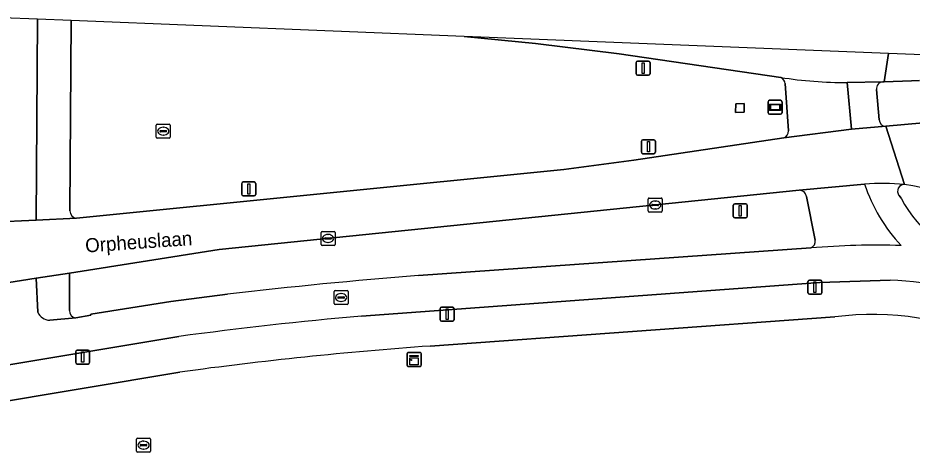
# Model space of a CAD drawing. Extents: x 161758 to 162722, y 384793 to 385405.
# Drawn here: x 161913.2 to 161977.1, y 385354.7 to 385385.7 of the extents above; entities that cross this region are included whole.
import ezdxf

# ---------------------------------------------------------------- set-up
doc = ezdxf.new("R2010")
doc.units = 0
for name, color, linetype in [('IMGEO_Berm_gesloten', 7, 'Continuous'), ('IMGEO_Berm_groen', 7, 'Continuous'), ('IMGEO_Fietspad_gesloten', 7, 'Continuous'), ('IMGEO_Groenvoorziening', 7, 'Continuous'), ('IMGEO_Kast', 7, 'Continuous'), ('IMGEO_Kolk', 7, 'Continuous'), ('IMGEO_Lichtmast', 7, 'Continuous'), ('IMGEO_Openbare_ruimte_label', 7, 'Continuous'), ('IMGEO_Rijbaan_lokaal_gesloten', 7, 'Continuous'), ('IMGEO_Rioolput', 7, 'Continuous'), ('IMGEO_Straatnaambord', 7, 'Continuous'), ('IMGEO_Terreindeel_open', 7, 'Continuous'), ('IMGEO_Verkeersbordpaal', 7, 'Continuous'), ('IMGEO_Verkeerseiland_gesloten', 7, 'Continuous'), ('IMGEO_Voetpad_open', 7, 'Continuous')]:
    doc.layers.add(name, color=color, linetype=linetype)

msp = doc.modelspace()

# ---------------------------------------------------------------- linework, layer by layer
at = {"layer": 'IMGEO_Berm_gesloten'}
msp.add_lwpolyline([(161976.151, 385373.042), (161976.299, 385372.83)], dxfattribs=at)
for centre, radius, start, end in [((161976.532, 385373.339), 0.483, 87.56385, 217.90438), ((161974.637, 385360.427), 13.531, 42.06056, 81.86032), ((161984.403, 385377.16), 9.188, 208.11884, 257.97269)]:
    msp.add_arc(centre, radius, start, end, dxfattribs=at)
at = {"layer": 'IMGEO_Berm_groen'}
for points in [[(161945.103, 385384.393), (161917.049, 385385.522), (161916.952, 385371.936)], [(161967.708, 385381.461), (161956.161, 385383.144), (161950.192, 385383.892), (161945.103, 385384.393)], [(161968.253, 385377.641), (161968.024, 385381.02)], [(161917.416, 385371.401), (161952.219, 385374.897), (161957.216, 385375.545), (161967.929, 385377.148)], [(161969.028, 385373.402), (161927.597, 385369.17), (161916.923, 385367.494), (161916.916, 385364.811)], [(161970.163, 385369.853), (161969.539, 385372.958)], [(161941.846, 385367.307), (161969.866, 385369.286)], [(161917.367, 385364.291), (161918.442, 385364.486), (161918.434, 385364.558), (161924.166, 385365.467), (161928.204, 385365.982)]]:
    msp.add_lwpolyline(points, dxfattribs=at)
msp.add_lwpolyline([(161964.504, 385379.586), (161965.1, 385379.595), (161965.105, 385378.974), (161964.466, 385378.952)], close=True, dxfattribs=at)
for centre, radius, start, end in [((161967.467, 385380.954), 0.561, 6.7151, 64.53213), ((161967.777, 385377.601), 0.477, 288.51413, 4.85997), ((161969.053, 385372.915), 0.488, 5.1004, 92.92586), ((161917.53, 385371.969), 0.579, 183.2499, 258.61963), ((161969.646, 385369.762), 0.525, 294.7652, 9.94285), ((161968.474, 385022.259), 346.074, 94.41287, 96.68221), ((161917.428, 385364.799), 0.512, 178.69969, 263.17101)]:
    msp.add_arc(centre, radius, start, end, dxfattribs=at)
at = {"layer": 'IMGEO_Fietspad_gesloten'}
for points in [[(161911.4, 385371.127), (161914.544, 385371.27), (161914.64, 385385.619), (161912.146, 385385.719)], [(161974.985, 385381.151), (161972.454, 385381.101), (161972.759, 385377.761), (161975.203, 385377.974)], [(161974.742, 385378.438), (161974.546, 385380.611)], [(161976.299, 385372.83), (161976.151, 385373.042)], [(161969.866, 385369.286), (161941.846, 385367.307)], [(161914.653, 385364.708), (161914.537, 385367.119), (161912.002, 385366.721), (161911.851, 385366.698), (161911.988, 385366.021), (161911.987, 385365.957), (161911.985, 385365.893), (161911.981, 385365.829)], [(161937.781, 385364.42), (161970.497, 385366.829), (161975.511, 385366.99)], [(161928.204, 385365.982), (161924.166, 385365.467), (161918.434, 385364.558), (161918.442, 385364.486), (161917.367, 385364.291), (161915.514, 385364.129)], [(161909.275, 385360.387), (161924.722, 385362.965)]]:
    msp.add_lwpolyline(points, dxfattribs=at)
for centre, radius, start, end in [((161975.027, 385380.669), 0.484, 94.94392, 186.83642), ((161975.206, 385378.438), 0.464, 180.04152, 269.58683), ((161975.002, 385356.017), 17.873, 85.02278, 94.21729), ((161985.393, 385377.833), 12.367, 198.83171, 222.65699), ((161976.532, 385373.339), 0.483, 87.56385, 217.90438), ((161984.403, 385377.16), 9.188, 208.11884, 257.97269), ((161974.487, 385315.26), 54.223, 88.0859, 94.88867), ((161968.474, 385022.259), 346.074, 94.41287, 96.68221), ((161974.467, 385343.268), 23.745, 65.72803, 87.48046), ((161915.506, 385365.047), 0.918, 201.65335, 270.50705), ((161964.956, 385061.189), 304.447, 95.121, 97.59406)]:
    msp.add_arc(centre, radius, start, end, dxfattribs=at)
at = {"layer": 'IMGEO_Groenvoorziening'}
for points in [[(161971.573, 385364.366), (161942.672, 385362.279)], [(161924.792, 385360.416), (161910.683, 385358.067)]]:
    msp.add_lwpolyline(points, dxfattribs=at)
for centre, radius, start, end in [((161974.266, 385343.076), 21.459, 65.15824, 97.20826), ((161963.563, 385075.051), 287.987, 94.15989, 97.73701)]:
    msp.add_arc(centre, radius, start, end, dxfattribs=at)
at = {"layer": 'IMGEO_Kast'}
for p, q in [((161941.029, 385360.894), (161941.029, 385361.735)), ((161941.029, 385361.735), (161941.029, 385360.894)), ((161941.104, 385361.819), (161941.945, 385361.819)), ((161941.945, 385361.819), (161941.104, 385361.819)), ((161942.029, 385361.744), (161942.029, 385360.903)), ((161942.029, 385360.903), (161942.029, 385361.744)), ((161941.954, 385360.819), (161941.113, 385360.819)), ((161941.113, 385360.819), (161941.954, 385360.819))]:
    msp.add_line(p, q, dxfattribs=at)
for points in [[(161941.224, 385361.609), (161941.824, 385361.609), (161941.824, 385361.524), (161941.224, 385361.524), (161941.224, 385361.609)], [(161941.224, 385361.434), (161941.824, 385361.434), (161941.824, 385360.945), (161941.224, 385360.945), (161941.224, 385361.434)]]:
    msp.add_lwpolyline(points, dxfattribs=at)
msp.add_circle((161941.308, 385361.283), 0.0377, dxfattribs=at)
for centre, start, end in [((161941.107, 385361.741), 92.4484, 184.28452), ((161941.107, 385361.741), 92.4484, 184.28452), ((161941.951, 385361.741), 2.4484, 94.28452), ((161941.951, 385361.741), 2.4484, 94.28452), ((161941.107, 385360.897), 182.4484, 274.28452), ((161941.107, 385360.897), 182.4484, 274.28452), ((161941.951, 385360.897), 272.4484, 4.28452), ((161941.951, 385360.897), 272.4484, 4.28452)]:
    msp.add_arc(centre, 0.0779, start, end, dxfattribs=at)
at = {"layer": 'IMGEO_Kolk'}
for p, q in [((161958.244, 385371.926), (161958.244, 385372.778)), ((161958.319, 385372.852), (161959.171, 385372.852)), ((161959.245, 385372.778), (161959.245, 385371.926)), ((161958.503, 385372.346), (161958.503, 385372.358)), ((161958.941, 385372.309), (161958.543, 385372.309)), ((161958.546, 385372.395), (161958.944, 385372.395)), ((161958.732, 385372.632), (161958.757, 385372.632)), ((161958.987, 385372.358), (161958.987, 385372.346)), ((161959.171, 385371.852), (161958.319, 385371.852)), ((161958.755, 385372.072), (161958.73, 385372.072)), ((161934.882, 385369.539), (161934.882, 385370.391)), ((161934.957, 385370.465), (161935.809, 385370.465)), ((161935.37, 385370.245), (161935.395, 385370.245)), ((161935.883, 385370.391), (161935.883, 385369.539)), ((161935.141, 385369.959), (161935.141, 385369.971)), ((161935.579, 385369.922), (161935.181, 385369.922)), ((161935.184, 385370.008), (161935.582, 385370.008)), ((161935.393, 385369.685), (161935.368, 385369.685)), ((161935.625, 385369.971), (161935.625, 385369.959)), ((161935.809, 385369.465), (161934.957, 385369.465))]:
    msp.add_line(p, q, dxfattribs=at)
for points in [[(161958.244, 385371.926), (161958.244, 385372.778)], [(161958.319, 385372.852), (161959.171, 385372.852)], [(161959.245, 385372.778), (161959.245, 385371.926)], [(161959.171, 385371.852), (161958.319, 385371.852)], [(161934.882, 385369.539), (161934.882, 385370.391)], [(161934.957, 385370.465), (161935.809, 385370.465)], [(161935.883, 385370.391), (161935.883, 385369.539)], [(161935.809, 385369.465), (161934.957, 385369.465)]]:
    msp.add_lwpolyline(points, dxfattribs=at)
for centre, radius, start, end in [((161958.321, 385372.776), 0.0765, 91.55205, 178.44795), ((161958.321, 385372.776), 0.0765, 91.55205, 178.44795), ((161959.169, 385372.776), 0.0765, 1.55205, 88.44795), ((161959.169, 385372.776), 0.0765, 1.55205, 88.44795), ((161958.543, 385372.355), 0.0403, 85.87752, 175.75265), ((161958.54, 385372.345), 0.0366, 178.93798, 274.71019), ((161958.944, 385372.352), 0.043, 264.86636, 352.45326), ((161958.948, 385372.357), 0.0386, 1.73085, 96.63898), ((161958.321, 385371.928), 0.0765, 181.55205, 268.44795), ((161958.321, 385371.928), 0.0765, 181.55205, 268.44795), ((161959.169, 385371.928), 0.0765, 271.55205, 358.44795), ((161959.169, 385371.928), 0.0765, 271.55205, 358.44795), ((161934.959, 385370.389), 0.0765, 91.55205, 178.44795), ((161934.959, 385370.389), 0.0765, 91.55205, 178.44795), ((161935.807, 385370.389), 0.0765, 1.55205, 88.44795), ((161935.807, 385370.389), 0.0765, 1.55205, 88.44795), ((161935.181, 385369.968), 0.0403, 85.87752, 175.75265), ((161935.178, 385369.958), 0.0366, 178.93798, 274.71019), ((161935.582, 385369.965), 0.043, 264.86636, 352.45326), ((161935.586, 385369.97), 0.0386, 1.73085, 96.63898), ((161934.959, 385369.541), 0.0765, 181.55205, 268.44795), ((161934.959, 385369.541), 0.0765, 181.55205, 268.44795), ((161935.807, 385369.541), 0.0765, 271.55205, 358.44795), ((161935.807, 385369.541), 0.0765, 271.55205, 358.44795)]:
    msp.add_arc(centre, radius, start, end, dxfattribs=at)
for centre, major_axis, ratio, start_param, end_param in [((161958.731, 385372.352), (-0.387, 0.002), 0.722429, 4.712389, 7.853982), ((161958.756, 385372.352), (-0.39, 0.002), 0.717154, 1.570796, 4.712389), ((161935.369, 385369.965), (-0.387, 0.002), 0.722429, 4.712389, 7.853982), ((161935.394, 385369.965), (-0.39, 0.002), 0.717154, 1.570796, 4.712389)]:
    msp.add_ellipse(centre, major_axis=major_axis, ratio=ratio, start_param=start_param, end_param=end_param, dxfattribs=at)
at = {"layer": 'IMGEO_Lichtmast'}
for p, q in [((161957.384, 385381.724), (161957.384, 385382.524)), ((161957.384, 385382.524), (161957.384, 385381.724)), ((161957.484, 385382.624), (161958.274, 385382.624)), ((161958.274, 385382.624), (161957.484, 385382.624)), ((161958.374, 385382.524), (161958.374, 385381.724)), ((161958.374, 385381.724), (161958.374, 385382.524)), ((161958.274, 385381.624), (161957.484, 385381.624)), ((161957.484, 385381.624), (161958.274, 385381.624)), ((161957.762, 385376.116), (161957.762, 385376.916)), ((161957.762, 385376.916), (161957.762, 385376.116)), ((161957.862, 385377.016), (161958.652, 385377.016)), ((161958.652, 385377.016), (161957.862, 385377.016)), ((161958.752, 385376.916), (161958.752, 385376.116)), ((161958.752, 385376.116), (161958.752, 385376.916)), ((161958.652, 385376.016), (161957.862, 385376.016)), ((161957.862, 385376.016), (161958.652, 385376.016)), ((161929.225, 385373.098), (161929.225, 385373.898)), ((161929.225, 385373.898), (161929.225, 385373.098)), ((161929.325, 385373.998), (161930.115, 385373.998)), ((161930.115, 385373.998), (161929.325, 385373.998)), ((161930.215, 385373.898), (161930.215, 385373.098)), ((161930.215, 385373.098), (161930.215, 385373.898)), ((161930.115, 385372.998), (161929.325, 385372.998)), ((161929.325, 385372.998), (161930.115, 385372.998)), ((161969.651, 385366.081), (161969.651, 385366.881)), ((161969.651, 385366.881), (161969.651, 385366.081)), ((161969.751, 385366.981), (161970.541, 385366.981)), ((161970.541, 385366.981), (161969.751, 385366.981)), ((161970.641, 385366.881), (161970.641, 385366.081)), ((161970.641, 385366.081), (161970.641, 385366.881)), ((161970.541, 385365.981), (161969.751, 385365.981)), ((161969.751, 385365.981), (161970.541, 385365.981)), ((161943.39, 385364.155), (161943.39, 385364.955)), ((161943.39, 385364.955), (161943.39, 385364.155)), ((161943.49, 385365.055), (161944.28, 385365.055)), ((161944.28, 385365.055), (161943.49, 385365.055)), ((161944.38, 385364.955), (161944.38, 385364.155)), ((161944.38, 385364.155), (161944.38, 385364.955)), ((161944.28, 385364.055), (161943.49, 385364.055)), ((161943.49, 385364.055), (161944.28, 385364.055)), ((161917.461, 385361.995), (161918.251, 385361.995)), ((161918.251, 385361.995), (161917.461, 385361.995)), ((161917.361, 385361.095), (161917.361, 385361.895)), ((161917.361, 385361.895), (161917.361, 385361.095)), ((161918.351, 385361.895), (161918.351, 385361.095)), ((161918.351, 385361.095), (161918.351, 385361.895)), ((161918.251, 385360.995), (161917.461, 385360.995)), ((161917.461, 385360.995), (161918.251, 385360.995))]:
    msp.add_line(p, q, dxfattribs=at)
for points in [[(161957.804, 385382.499), (161957.954, 385382.499), (161957.954, 385381.749), (161957.804, 385381.749), (161957.804, 385382.499)], [(161958.182, 385376.891), (161958.332, 385376.891), (161958.332, 385376.141), (161958.182, 385376.141), (161958.182, 385376.891)], [(161929.645, 385373.873), (161929.795, 385373.873), (161929.795, 385373.123), (161929.645, 385373.123), (161929.645, 385373.873)], [(161970.071, 385366.856), (161970.221, 385366.856), (161970.221, 385366.106), (161970.071, 385366.106), (161970.071, 385366.856)], [(161943.81, 385364.93), (161943.96, 385364.93), (161943.96, 385364.18), (161943.81, 385364.18), (161943.81, 385364.93)], [(161917.781, 385361.87), (161917.931, 385361.87), (161917.931, 385361.12), (161917.781, 385361.12), (161917.781, 385361.87)]]:
    msp.add_lwpolyline(points, dxfattribs=at)
for centre, start, end in [((161957.484, 385382.524), 90, 180), ((161957.484, 385382.524), 90, 180), ((161958.274, 385382.524), 0, 90), ((161958.274, 385382.524), 360, 90), ((161957.484, 385381.724), 180, 270), ((161957.484, 385381.724), 180, 270), ((161958.274, 385381.724), 270, 0), ((161958.274, 385381.724), 270, 0), ((161957.862, 385376.916), 90, 180), ((161957.862, 385376.916), 90, 180), ((161958.652, 385376.916), 0, 90), ((161958.652, 385376.916), 360, 90), ((161957.862, 385376.116), 180, 270), ((161957.862, 385376.116), 180, 270), ((161958.652, 385376.116), 270, 0), ((161958.652, 385376.116), 270, 0), ((161929.325, 385373.898), 90, 180), ((161929.325, 385373.898), 90, 180), ((161930.115, 385373.898), 0, 90), ((161930.115, 385373.898), 360, 90), ((161929.325, 385373.098), 180, 270), ((161929.325, 385373.098), 180, 270), ((161930.115, 385373.098), 270, 0), ((161930.115, 385373.098), 270, 0), ((161969.751, 385366.881), 90, 180), ((161969.751, 385366.881), 90, 180), ((161970.541, 385366.881), 0, 90), ((161970.541, 385366.881), 360, 90), ((161969.751, 385366.081), 180, 270), ((161969.751, 385366.081), 180, 270), ((161970.541, 385366.081), 270, 0), ((161970.541, 385366.081), 270, 0), ((161943.49, 385364.955), 90, 180), ((161943.49, 385364.955), 90, 180), ((161944.28, 385364.955), 0, 90), ((161944.28, 385364.955), 360, 90), ((161943.49, 385364.155), 180, 270), ((161943.49, 385364.155), 180, 270), ((161944.28, 385364.155), 270, 0), ((161944.28, 385364.155), 270, 0), ((161917.461, 385361.895), 90, 180), ((161917.461, 385361.895), 90, 180), ((161918.251, 385361.895), 0, 90), ((161918.251, 385361.895), 360, 90), ((161917.461, 385361.095), 180, 270), ((161917.461, 385361.095), 180, 270), ((161918.251, 385361.095), 270, 0), ((161918.251, 385361.095), 270, 0)]:
    msp.add_arc(centre, 0.1, start, end, dxfattribs=at)
at = {"layer": 'IMGEO_Rijbaan_lokaal_gesloten'}
for points in [[(161975.392, 385383.175), (161945.103, 385384.393), (161950.192, 385383.892), (161956.161, 385383.144), (161967.708, 385381.461)], [(161972.454, 385381.101), (161974.985, 385381.151), (161975.099, 385381.155), (161975.392, 385383.175)], [(161975.392, 385383.175), (161975.099, 385381.155), (161977.036, 385381.228), (161977.622, 385381.235)], [(161985.172, 385382.782), (161975.392, 385383.175)], [(161976.553, 385373.822), (161975.203, 385377.974), (161972.759, 385377.761), (161967.929, 385377.148), (161957.216, 385375.545), (161952.219, 385374.897), (161917.416, 385371.401), (161914.544, 385371.27), (161911.4, 385371.127), (161911.18, 385371.117), (161905.327, 385370.85)], [(161977.887, 385378.221), (161975.203, 385377.974), (161976.553, 385373.822)], [(161890.228, 385372.905), (161889.159, 385372.498), (161888.671, 385372.472), (161887.405, 385372.41), (161886.93, 385365.469), (161891.907, 385365.74), (161899.549, 385366.47), (161904.533, 385366.946), (161911.851, 385366.698), (161912.002, 385366.721), (161914.537, 385367.119), (161916.923, 385367.494), (161927.597, 385369.17), (161969.028, 385373.402)], [(161969.028, 385373.402), (161973.688, 385373.841)]]:
    msp.add_lwpolyline(points, dxfattribs=at)
for centre, radius, start, end in [((161972.504, 385413.223), 32.122, 261.4135, 269.91096), ((161975.002, 385356.017), 17.873, 85.02278, 94.21729), ((161974.637, 385360.427), 13.531, 42.06056, 81.86032)]:
    msp.add_arc(centre, radius, start, end, dxfattribs=at)
at = {"layer": 'IMGEO_Rioolput'}
for p, q in [((161923.114, 385377.199), (161923.114, 385378.051)), ((161923.189, 385378.125), (161924.041, 385378.125)), ((161923.602, 385377.905), (161923.627, 385377.905)), ((161924.115, 385378.051), (161924.115, 385377.199)), ((161923.373, 385377.619), (161923.373, 385377.631)), ((161923.811, 385377.582), (161923.413, 385377.582)), ((161923.416, 385377.668), (161923.814, 385377.668)), ((161923.625, 385377.345), (161923.6, 385377.345)), ((161923.857, 385377.631), (161923.857, 385377.619)), ((161924.041, 385377.125), (161923.189, 385377.125)), ((161935.812, 385365.317), (161935.812, 385366.169)), ((161935.887, 385366.243), (161936.739, 385366.243)), ((161936.071, 385365.737), (161936.071, 385365.749)), ((161936.114, 385365.786), (161936.512, 385365.786)), ((161936.3, 385366.023), (161936.325, 385366.023)), ((161936.555, 385365.749), (161936.555, 385365.737)), ((161936.813, 385366.169), (161936.813, 385365.317)), ((161936.739, 385365.243), (161935.887, 385365.243)), ((161936.509, 385365.7), (161936.111, 385365.7)), ((161936.323, 385365.463), (161936.298, 385365.463)), ((161921.709, 385354.776), (161921.709, 385355.628)), ((161921.784, 385355.702), (161922.636, 385355.702)), ((161922.71, 385355.628), (161922.71, 385354.776)), ((161921.968, 385355.196), (161921.968, 385355.208)), ((161922.406, 385355.159), (161922.008, 385355.159)), ((161922.011, 385355.245), (161922.409, 385355.245)), ((161922.22, 385354.922), (161922.195, 385354.922)), ((161922.197, 385355.482), (161922.222, 385355.482)), ((161922.452, 385355.208), (161922.452, 385355.196)), ((161922.636, 385354.702), (161921.784, 385354.702))]:
    msp.add_line(p, q, dxfattribs=at)
for points in [[(161923.114, 385377.199), (161923.114, 385378.051)], [(161923.189, 385378.125), (161924.041, 385378.125)], [(161924.115, 385378.051), (161924.115, 385377.199)], [(161924.041, 385377.125), (161923.189, 385377.125)], [(161935.812, 385365.317), (161935.812, 385366.169)], [(161935.887, 385366.243), (161936.739, 385366.243)], [(161936.813, 385366.169), (161936.813, 385365.317)], [(161936.739, 385365.243), (161935.887, 385365.243)], [(161921.709, 385354.776), (161921.709, 385355.628)], [(161921.784, 385355.702), (161922.636, 385355.702)], [(161922.71, 385355.628), (161922.71, 385354.776)], [(161922.636, 385354.702), (161921.784, 385354.702)]]:
    msp.add_lwpolyline(points, dxfattribs=at)
for centre, radius, start, end in [((161923.191, 385378.049), 0.0765, 91.55205, 178.44795), ((161923.191, 385378.049), 0.0765, 91.55205, 178.44795), ((161924.039, 385378.049), 0.0765, 1.55205, 88.44795), ((161924.039, 385378.049), 0.0765, 1.55205, 88.44795), ((161923.413, 385377.628), 0.0403, 85.87752, 175.75265), ((161923.41, 385377.618), 0.0366, 178.93798, 274.71019), ((161923.814, 385377.625), 0.043, 264.86636, 352.45326), ((161923.818, 385377.63), 0.0386, 1.73085, 96.63898), ((161923.191, 385377.201), 0.0765, 181.55205, 268.44795), ((161923.191, 385377.201), 0.0765, 181.55205, 268.44795), ((161924.039, 385377.201), 0.0765, 271.55205, 358.44795), ((161924.039, 385377.201), 0.0765, 271.55205, 358.44795), ((161935.889, 385366.167), 0.0765, 91.55205, 178.44795), ((161935.889, 385366.167), 0.0765, 91.55205, 178.44795), ((161936.111, 385365.746), 0.0403, 85.87752, 175.75265), ((161936.516, 385365.748), 0.0386, 1.73085, 96.63898), ((161936.737, 385366.167), 0.0765, 1.55205, 88.44795), ((161936.737, 385366.167), 0.0765, 1.55205, 88.44795), ((161935.889, 385365.319), 0.0765, 181.55205, 268.44795), ((161935.889, 385365.319), 0.0765, 181.55205, 268.44795), ((161936.108, 385365.736), 0.0366, 178.93798, 274.71019), ((161936.512, 385365.743), 0.043, 264.86636, 352.45326), ((161936.737, 385365.319), 0.0765, 271.55205, 358.44795), ((161936.737, 385365.319), 0.0765, 271.55205, 358.44795), ((161921.786, 385355.626), 0.0765, 91.55205, 178.44795), ((161921.786, 385355.626), 0.0765, 91.55205, 178.44795), ((161922.634, 385355.626), 0.0765, 1.55205, 88.44795), ((161922.634, 385355.626), 0.0765, 1.55205, 88.44795), ((161922.008, 385355.205), 0.0403, 85.87752, 175.75265), ((161922.005, 385355.195), 0.0366, 178.93798, 274.71019), ((161922.409, 385355.202), 0.043, 264.86636, 352.45326), ((161922.413, 385355.207), 0.0386, 1.73085, 96.63898), ((161921.786, 385354.778), 0.0765, 181.55205, 268.44795), ((161921.786, 385354.778), 0.0765, 181.55205, 268.44795), ((161922.634, 385354.778), 0.0765, 271.55205, 358.44795), ((161922.634, 385354.778), 0.0765, 271.55205, 358.44795)]:
    msp.add_arc(centre, radius, start, end, dxfattribs=at)
for centre, major_axis, ratio, start_param, end_param in [((161923.601, 385377.625), (-0.387, 0.002), 0.722429, 4.712389, 7.853982), ((161923.626, 385377.625), (-0.39, 0.002), 0.717154, 1.570796, 4.712389), ((161936.299, 385365.743), (-0.387, 0.002), 0.722429, 4.712389, 7.853982), ((161936.324, 385365.743), (-0.39, 0.002), 0.717154, 1.570796, 4.712389), ((161922.196, 385355.202), (-0.387, 0.002), 0.722429, 4.712389, 7.853982), ((161922.221, 385355.202), (-0.39, 0.002), 0.717154, 1.570796, 4.712389)]:
    msp.add_ellipse(centre, major_axis=major_axis, ratio=ratio, start_param=start_param, end_param=end_param, dxfattribs=at)
at = {"layer": 'IMGEO_Straatnaambord'}
for p, q in [((161966.909, 385379.833), (161967.699, 385379.833)), ((161967.699, 385379.833), (161966.909, 385379.833)), ((161966.809, 385378.933), (161966.809, 385379.733)), ((161966.809, 385379.733), (161966.809, 385378.933)), ((161967.799, 385379.733), (161967.799, 385378.933)), ((161967.799, 385378.933), (161967.799, 385379.733)), ((161967.699, 385378.833), (161966.909, 385378.833)), ((161966.909, 385378.833), (161967.699, 385378.833))]:
    msp.add_line(p, q, dxfattribs=at)
for points in [[(161966.91, 385379.565), (161967.698, 385379.565), (161967.698, 385379.101), (161966.91, 385379.101), (161966.91, 385379.565)], [(161966.975, 385379.5), (161966.975, 385379.166), (161967.633, 385379.166), (161967.633, 385379.5), (161966.975, 385379.5)]]:
    msp.add_lwpolyline(points, dxfattribs=at)
for centre, start, end in [((161966.909, 385379.733), 90, 180), ((161966.909, 385379.733), 90, 180), ((161967.699, 385379.733), 0, 90), ((161967.699, 385379.733), 360, 90), ((161966.909, 385378.933), 180, 270), ((161966.909, 385378.933), 180, 270), ((161967.699, 385378.933), 270, 0), ((161967.699, 385378.933), 270, 0)]:
    msp.add_arc(centre, 0.1, start, end, dxfattribs=at)
at = {"layer": 'IMGEO_Terreindeel_open'}
msp.add_lwpolyline([(161965.105, 385378.974), (161965.1, 385379.595), (161964.504, 385379.586), (161964.466, 385378.952)], close=True, dxfattribs=at)
at = {"layer": 'IMGEO_Verkeersbordpaal'}
for p, q in [((161964.317, 385371.54), (161964.317, 385372.34)), ((161964.317, 385372.34), (161964.317, 385371.54)), ((161964.417, 385372.44), (161965.207, 385372.44)), ((161965.207, 385372.44), (161964.417, 385372.44)), ((161965.307, 385372.34), (161965.307, 385371.54)), ((161965.307, 385371.54), (161965.307, 385372.34)), ((161965.207, 385371.44), (161964.417, 385371.44)), ((161964.417, 385371.44), (161965.207, 385371.44))]:
    msp.add_line(p, q, dxfattribs=at)
msp.add_lwpolyline([(161964.737, 385372.315), (161964.887, 385372.315), (161964.887, 385371.565), (161964.737, 385371.565), (161964.737, 385372.315)], dxfattribs=at)
for centre, start, end in [((161964.417, 385372.34), 90, 180), ((161964.417, 385372.34), 90, 180), ((161965.207, 385372.34), 0, 90), ((161965.207, 385372.34), 360, 90), ((161964.417, 385371.54), 180, 270), ((161964.417, 385371.54), 180, 270), ((161965.207, 385371.54), 270, 0), ((161965.207, 385371.54), 270, 0)]:
    msp.add_arc(centre, 0.1, start, end, dxfattribs=at)
at = {"layer": 'IMGEO_Verkeerseiland_gesloten'}
for points in [[(161977.622, 385381.235), (161977.036, 385381.228), (161975.099, 385381.155), (161974.985, 385381.151)], [(161974.546, 385380.611), (161974.742, 385378.438)], [(161975.203, 385377.974), (161977.887, 385378.221)]]:
    msp.add_lwpolyline(points, dxfattribs=at)
for centre, radius, start, end in [((161975.027, 385380.669), 0.484, 94.94392, 186.83642), ((161975.206, 385378.438), 0.464, 180.04152, 269.58683)]:
    msp.add_arc(centre, radius, start, end, dxfattribs=at)
at = {"layer": 'IMGEO_Voetpad_open'}
for points in [[(161917.049, 385385.522), (161914.64, 385385.619), (161914.544, 385371.27), (161917.416, 385371.401)], [(161916.952, 385371.936), (161917.049, 385385.522)], [(161967.929, 385377.148), (161972.759, 385377.761), (161972.454, 385381.101)], [(161968.024, 385381.02), (161968.253, 385377.641)], [(161973.688, 385373.841), (161969.028, 385373.402)], [(161969.539, 385372.958), (161970.163, 385369.853)], [(161916.923, 385367.494), (161914.537, 385367.119), (161914.653, 385364.708)], [(161916.916, 385364.811), (161916.923, 385367.494)], [(161975.511, 385366.99), (161970.497, 385366.829), (161937.781, 385364.42)], [(161915.514, 385364.129), (161917.367, 385364.291)], [(161942.672, 385362.279), (161971.573, 385364.366)], [(161924.722, 385362.965), (161909.275, 385360.387), (161908.95, 385356.368)], [(161910.683, 385358.067), (161924.792, 385360.416)]]:
    msp.add_lwpolyline(points, dxfattribs=at)
for centre, radius, start, end in [((161972.504, 385413.223), 32.122, 261.4135, 269.91096), ((161967.467, 385380.954), 0.561, 6.7151, 64.53213), ((161967.777, 385377.601), 0.477, 288.51413, 4.85997), ((161969.053, 385372.915), 0.488, 5.1004, 92.92586), ((161985.393, 385377.833), 12.367, 198.83171, 222.65699), ((161917.53, 385371.969), 0.579, 183.2499, 258.61963), ((161969.646, 385369.762), 0.525, 294.7652, 9.94285), ((161974.487, 385315.26), 54.223, 88.0859, 94.88867), ((161974.467, 385343.268), 23.745, 65.72803, 87.48046), ((161915.506, 385365.047), 0.918, 201.65335, 270.50705), ((161917.428, 385364.799), 0.512, 178.69969, 263.17101), ((161974.266, 385343.076), 21.459, 65.15824, 97.20826), ((161964.956, 385061.189), 304.447, 95.121, 97.59406), ((161963.563, 385075.051), 287.987, 94.15989, 97.73701)]:
    msp.add_arc(centre, radius, start, end, dxfattribs=at)

# ---------------------------------------------------------------- texts
at = {"layer": 'IMGEO_Openbare_ruimte_label'}
msp.add_text('Orpheuslaan', height=1, rotation=4.01217, dxfattribs=at).set_placement((161918.075, 385368.955))

doc.saveas('drawing.dxf')
